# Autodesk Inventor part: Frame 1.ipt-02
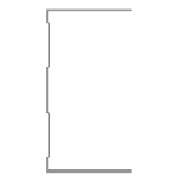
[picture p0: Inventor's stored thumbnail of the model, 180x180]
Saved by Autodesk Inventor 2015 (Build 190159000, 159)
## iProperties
IsCustomPart: 1
Created: 2015-04
Part Number: Frame 1.ipt-02
Material: Aluminum 6061
Description: Kévin Novo
Document SubType Name: Modeling
Standard: Kevin
Designer: suporte
Standards Organization: Kevin
Language: en-US
Size Designation: (Unnamed 2)
Categories: <MemberInstance><Categories><Category DisplayName="Structural Shapes" InternalName="089c4875-fa83-4c05-b084-43b9cc11f5ed" Mnemonic="GRDR"><CategoryParameter Dis
Density: 2.7 g/cm^3
Appearance: Aluminum - Flat
_CCFamilyMember: 2
_CCFamilyDisplayName: Kévin - Kévin Novo
_FrameMemberDoc: Frame Member File
_Version: 15.0.0
_GetPNFromCC: 1
G_W: 50,000 mm
G_H: 75,000 mm
G_L: 2100,000 mm
+408B6D46-B3B8-4F2C-9FFE-DDDB600CEF3B+CUTDETAIL1: Notch
+A0019AE7-BB96-4E3E-B061-243E1C635B72+CUTDETAIL2: Notch
Author: suporte
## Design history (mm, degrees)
node "Start Plane"
node "End Plane"
sketch "Sketch"
  geometry: L1 (24.7, 37.5)-(24.7, 36.9); L2 (24.7, 36.9)-(-24.7, 36.9); L3 (-24.7, -36.9)-(24.7, -36.9); L4 (24.7, -36.9)-(24.7, -37.5); L5 (24.7, -37.5)-(-25.3, -37.5); L6 (-25.3, 37.5)-(24.7, 37.5); L7 (-24.7, 36.9)-(-24.7, 31.9); L8 (-24.7, 31.9)-(-23.3, 30.5); L9 (-23.3, 30.5)-(-23.3, 10.934); L10 (-23.3, 10.934)-(-24.7, 9.534); L11 (-24.7, 9.534)-(-24.7, -9.534); L12 (-24.7, -9.534)-(-23.3, -10.934); L13 (-23.3, -10.934)-(-23.3, -30.5); L14 (-23.3, -30.5)-(-24.7, -31.9); L15 (-24.7, -31.9)-(-24.7, -36.9); L16 (-25.3, -37.5)-(-25.3, -31.651); L17 (-25.3, -31.651)-(-23.9, -30.251); L18 (-23.9, -30.251)-(-23.9, -11.183); L19 (-23.9, -11.183)-(-25.3, -9.783); L20 (-25.3, -9.783)-(-25.3, 9.783); L21 (-25.3, 9.783)-(-23.9, 11.183); L22 (-23.9, 11.183)-(-23.9, 30.251); L23 (-23.9, 30.251)-(-25.3, 31.651); L24 (-25.3, 31.651)-(-25.3, 37.5); L25 (-25.3, 0)-(30.37, 0); 3 further points
  constraints: 50 end point, 10 point on line, 9 parallel, 5 perpendicular, 4 equal length, 3 midpoint, 3 vertical, 2 vertical alignment, 1 collinear, 1 horizontal, 1 horizontal alignment
  dimensions: "d3" = 0.6 distance of L1.start L1.end (= d6); "d5" = 75 distance between parallel lines of L5 L6; "d6" = 0.6 distance between parallel lines of L24 L7 (= d8); "d7" = 0.6 distance between parallel lines of L8 L23 (= d8); "d8" = 0.6 distance between parallel lines of L22 L9 (= d12); "Espessura" = 0.6 distance between parallel lines of L17 L14; "d10" = 0.6 distance between parallel lines of L13 L18 (= Espessura); "d11" = 0.6 distance between parallel lines of L12 L19 (= Espessura); "d12" = 0.6 distance between parallel lines of L21 L10 (= d11); "d13" = 5 distance of L2.end L7.end; "d15" = 135 deg angle of L9 L8; "d16" = 2 distance between parallel lines of L24 L9; "d17" = 50 distance of L6.start L1.start
extrude "Body" join sketch "Sketch" stored distance "d24" = 0.13; taper "d25" = 0 deg
node "Driven Length"
  sketch "Sketch10"
    geometry: L1 (0, 0)-(10, 0) reference
    constraints: 2 end point, 1 horizontal
  workplane "Work Plane7"
  sketch "Sketch11"
    geometry: L1 (-2, 0)-(12, 0) reference; L2 (-2, 2100)-(12, 2100) reference
    dimensions: "d27" = 2100 distance between parallel lines of L1 L2 (derived)
workplane "Work Plane8"
workplane "Work Plane9"
workplane "Work Plane10"
sketch "Sketch12"
  geometry: L1 (24.7, 37.5)-(24.7, 36.9); L2 (24.7, 36.9)-(-24.7, 36.9); L3 (-24.7, 36.9)-(-24.7, 31.9); L4 (-24.7, 31.9)-(-23.3, 30.5); L5 (-23.3, 30.5)-(-23.3, 10.934); L6 (-23.3, 10.934)-(-24.7, 9.534); L7 (-24.7, 9.534)-(-24.7, -9.534); L8 (-24.7, -9.534)-(-23.3, -10.934); L9 (-23.3, -10.934)-(-23.3, -30.5); L10 (-23.3, -30.5)-(-24.7, -31.9); L11 (-24.7, -31.9)-(-24.7, -36.9); L12 (-24.7, -36.9)-(24.7, -36.9); L13 (24.7, -36.9)-(24.7, -37.5); L14 (24.7, -37.5)-(-25.3, -37.5); L15 (-25.3, -37.5)-(-25.3, -31.651); L16 (-25.3, -31.651)-(-23.9, -30.251); L17 (-23.9, -30.251)-(-23.9, -11.183); L18 (-23.9, -11.183)-(-25.3, -9.783); L19 (-25.3, -9.783)-(-25.3, 9.783); L20 (-25.3, 9.783)-(-23.9, 11.183); L21 (-23.9, 11.183)-(-23.9, 30.251); L22 (-23.9, 30.251)-(-25.3, 31.651); L23 (-25.3, 31.651)-(-25.3, 37.5); L24 (-25.3, 37.5)-(24.7, 37.5)
  constraints: 48 end point, 10 point on line
extrude "Extrusion3" cut sketch "Sketch12" stored distance "d36" = 0.13; taper "d37" = 0 deg
workplane "Work Plane11"
workplane "Work Plane12"
workplane "Work Plane13"
sketch "Sketch13"
  geometry: L1 (24.7, 37.5)-(24.7, 36.9); L2 (24.7, 36.9)-(-24.7, 36.9); L3 (-24.7, 36.9)-(-24.7, 31.9); L4 (-24.7, 31.9)-(-23.3, 30.5); L5 (-23.3, 30.5)-(-23.3, 10.934); L6 (-23.3, 10.934)-(-24.7, 9.534); L7 (-24.7, 9.534)-(-24.7, -9.534); L8 (-24.7, -9.534)-(-23.3, -10.934); L9 (-23.3, -10.934)-(-23.3, -30.5); L10 (-23.3, -30.5)-(-24.7, -31.9); L11 (-24.7, -31.9)-(-24.7, -36.9); L12 (-24.7, -36.9)-(24.7, -36.9); L13 (24.7, -36.9)-(24.7, -37.5); L14 (24.7, -37.5)-(-25.3, -37.5); L15 (-25.3, -37.5)-(-25.3, -31.651); L16 (-25.3, -31.651)-(-23.9, -30.251); L17 (-23.9, -30.251)-(-23.9, -11.183); L18 (-23.9, -11.183)-(-25.3, -9.783); L19 (-25.3, -9.783)-(-25.3, 9.783); L20 (-25.3, 9.783)-(-23.9, 11.183); L21 (-23.9, 11.183)-(-23.9, 30.251); L22 (-23.9, 30.251)-(-25.3, 31.651); L23 (-25.3, 31.651)-(-25.3, 37.5); L24 (-25.3, 37.5)-(24.7, 37.5)
  constraints: 48 end point, 10 point on line
extrude "Extrusion4" cut sketch "Sketch13" stored distance "d38" = 0.13; taper "d39" = 0 deg
body "Solid1"
other parameters: "G_OFFSET_START" = 0 [user parameter; used in 1 equation term], "G_OFFSET_END" = 0 [user parameter; used in 1 equation term], "d22" = 0 (computed from G_OFFSET_START), "G_L" = 2100 (= d27) [user parameter], "d34" = 90 deg
